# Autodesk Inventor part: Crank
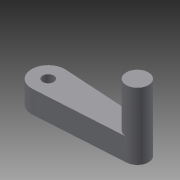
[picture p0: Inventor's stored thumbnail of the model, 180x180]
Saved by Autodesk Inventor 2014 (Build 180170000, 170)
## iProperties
Created: 2013-11
Part Number: Crank
Material: Generic
Document SubType Name: Modeling
Designer: 603839
Density: 1 g/cm^3
Appearance: Default
Mass: 17.892 g
Surface Area: 61.0566 cm^2
Volume: 17.892 cm^3
Author: 603839
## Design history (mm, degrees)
sketch "Sketch1"
  geometry: C1 r 3.175 at (0, 0); 1 further point
  constraints: 1 centre point, 1 coincident
  dimensions: "d0" = 6.35 diameter of C1
extrude "Extrusion1" new body sketch "Sketch1" distance "d1" = 38.1; taper "d2" = 0 deg
sketch "Sketch2"
  geometry: C1 r 3.175 at (0, 0) reference
extrude "Extrusion2" join sketch "Sketch2" distance "d3" = 12.7; taper "d4" = 0 deg
sketch "Sketch3"
  geometry: C1 r 3.175 at (0, 0) reference
extrude "Extrusion3" join sketch "Sketch3" distance "d5" = 12.7; taper "d6" = 0 deg
sketch "Sketch4"
  geometry: C1 r 3.175 at (0, 0) reference; C2 r 9.525 at (0, 0)
  constraints: 1 centre point, 1 coincident
  dimensions: "d7" = 19.05 diameter of C2
extrude "Extrusion4" join sketch "Sketch4" distance "d8" = 12.7; taper "d9" = 0 deg
sketch "Sketch5"
  geometry: L1 (0, -9.525)-(51.195, -6.338); L2 (0, 9.525)-(51.195, 6.338); A1 r 9.525 centre (0, 0) between (0, -9.525) and (0, 9.525) reference; A2 r 6.35 centre (50.8, 0) between (51.195, -6.338) and (51.195, 6.338)
  constraints: 4 end point, 4 point on circle, 2 tangent, 1 centre point
  dimensions: "d10" = 12.7 diameter of A2
extrude "Extrusion5" join sketch "Sketch5" distance "d11" = 12.7; taper "d12" = 0 deg
sketch "Sketch6"
  geometry: A1 r 6.35 centre (50.8, 0) between (51.195, 6.338) and (51.195, -6.338) reference; 1 further point
  constraints: 1 coincident, 3 other
extrude "Extrusion6" join sketch "Sketch6" distance "d13" = 25.4; taper "d15" = 0 deg; dims "d14" = 12.7, "d16" = 0
sketch "Sketch7"
  geometry: C1 r 3.175 at (0, 0) reference
extrude "Extrusion7" join sketch "Sketch7" distance "d17" = 6.35; taper "d18" = 0 deg
sketch "Sketch8"
  geometry: C1 r 3.175 at (0, 0) reference
extrude "Extrusion8" cut sketch "Sketch8" stored distance "d19" = 25.4; taper "d20" = 0 deg
body "Solid1"
